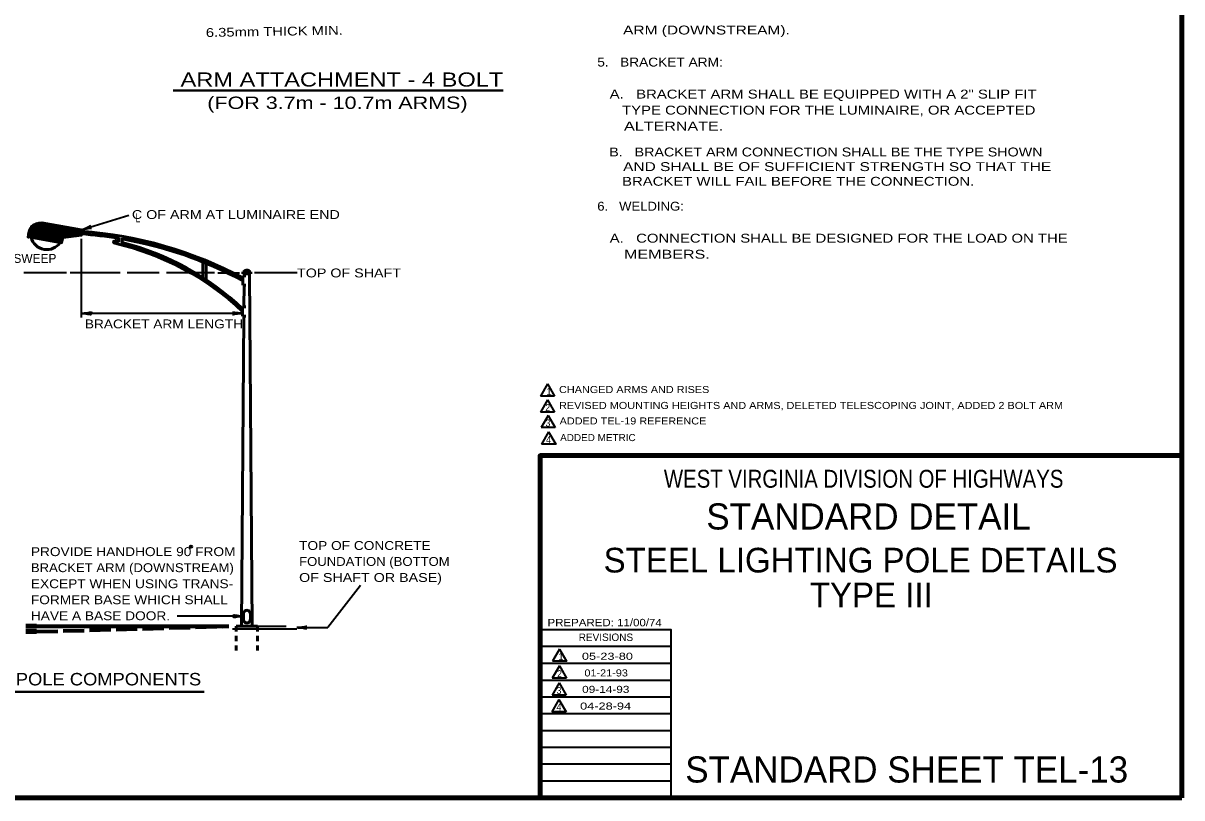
# Model space of a CAD drawing. Extents: x -23 to 690, y -228 to 443.
# Drawn here: x 356 to 684, y -0.6 to 218.8 of the extents above; entities that cross this region are included whole.
import ezdxf
from ezdxf.enums import TextEntityAlignment as Align

# ---------------------------------------------------------------- set-up
doc = ezdxf.new("R2010")
doc.units = 0
doc.header["$PDMODE"] = 32
doc.header["$PDSIZE"] = 0.5
doc.linetypes.add('LONG_DASHED', pattern=[7.5, 6, -1.5])
doc.linetypes.add('SHORT_DASHED', pattern=[2.7, 1.5, -1.2])
doc.layers.add('1', color=7, linetype='Continuous', lineweight=35)
doc.layers.add('61', color=7, linetype='Continuous', lineweight=35)

msp = doc.modelspace()

# ---------------------------------------------------------------- linework, layer by layer
at = {"layer": '1', "lineweight": 158}
for q in [(684.026, 437.805), (684.026, 96.305), (24.36, -0.611)]:
    msp.add_line((684.026, -0.611), q, dxfattribs=at)
at = {"layer": '1', "lineweight": 13}
msp.add_line((684.026, -0.611), (684.026, 437.805), dxfattribs=at)
at = {"layer": '1', "lineweight": 40}
for p, q in [((398.499, 199.759), (491.884, 199.759)), ((352.69, 29.414), (407.27, 29.414))]:
    msp.add_line(p, q, dxfattribs=at)
at = {"layer": '1'}
for p, q in [((372.45, 160.234), (385.87, 164.374)), ((372.45, 157.714), (372.45, 135.394)), ((368.291, 148.054), (356.21, 148.054)), ((383.411, 148.054), (369.31, 148.054)), ((394.51, 148.054), (385.43, 148.054)), ((410.13, 148.054), (396.53, 148.054)), ((411.13, 148.054), (417.19, 148.054)), ((433.57, 148.054), (421.47, 148.054)), ((418.13, 136.594), (372.45, 136.594)), ((504.445, 116.622), (502.445, 113.158)), ((504.445, 116.622), (506.445, 113.158)), ((506.445, 113.158), (502.445, 113.158)), ((504.445, 112.12), (502.445, 108.656)), ((504.445, 112.12), (506.445, 108.656)), ((506.445, 108.656), (502.445, 108.656)), ((504.612, 107.726), (502.612, 104.261)), ((504.612, 107.726), (506.612, 104.261)), ((506.612, 104.261), (502.612, 104.261)), ((504.76, 103.015), (502.76, 99.551)), ((451.49, 59.514), (442.231, 47.614)), ((418.39, 50.814), (399.55, 50.814)), ((415.291, 47.214), (433.43, 47.214)), ((422.351, 47.974), (430.411, 47.974)), ((433.43, 47.614), (442.231, 47.614)), ((539.443, 42.222), (502.36, 42.222)), ((507.823, 41.54), (505.823, 38.076)), ((539.443, 37.472), (502.36, 37.472)), ((507.788, 36.751), (505.788, 33.287)), ((507.788, 36.751), (509.788, 33.287)), ((509.788, 33.287), (505.788, 33.287)), ((539.443, 32.639), (502.36, 32.639)), ((507.746, 31.971), (505.746, 28.507)), ((507.746, 31.971), (509.746, 28.507)), ((539.443, 27.889), (502.36, 27.889)), ((507.692, 27.245), (505.692, 23.781)), ((509.746, 28.507), (505.746, 28.507)), ((507.692, 27.245), (509.692, 23.781)), ((539.443, 23.139), (502.36, 23.139)), ((509.692, 23.781), (505.692, 23.781)), ((539.443, 18.389), (502.36, 18.389)), ((539.443, 13.639), (502.36, 13.639)), ((539.443, 8.889), (502.36, 8.889)), ((539.443, 4.139), (502.36, 4.139))]:
    msp.add_line(p, q, dxfattribs=at)
at = {"layer": '1', "lineweight": 53}
for p, q in [((357.57, 159.554), (360.171, 162.134)), ((357.611, 159.674), (360.03, 162.094)), ((357.671, 159.834), (359.87, 162.054)), ((357.71, 159.994), (359.71, 161.994)), ((357.791, 160.194), (359.53, 161.914)), ((357.89, 160.394), (359.31, 161.814)), ((358.05, 160.654), (359.05, 161.654)), ((358.09, 159.954), (360.31, 162.154)), ((358.21, 159.954), (360.43, 162.194)), ((358.31, 159.954), (360.55, 162.194)), ((358.411, 159.954), (360.671, 162.214)), ((358.53, 159.954), (360.791, 162.214)), ((358.63, 159.954), (360.89, 162.214)), ((358.731, 159.954), (361.01, 162.214)), ((358.851, 159.954), (361.111, 162.214)), ((358.95, 159.954), (361.21, 162.214)), ((359.05, 159.954), (361.31, 162.214)), ((359.171, 159.954), (361.39, 162.194)), ((359.27, 159.954), (361.49, 162.174)), ((359.37, 159.954), (361.57, 162.154)), ((359.49, 159.954), (361.671, 162.134)), ((359.59, 159.954), (361.77, 162.134)), ((359.69, 159.954), (361.851, 162.114)), ((359.81, 159.954), (361.95, 162.094)), ((359.911, 159.954), (362.03, 162.074)), ((360.01, 159.954), (362.13, 162.054)), ((360.13, 159.954), (362.21, 162.054)), ((360.231, 159.954), (362.31, 162.034)), ((360.351, 159.954), (362.39, 162.014)), ((360.45, 159.954), (362.49, 161.994)), ((360.55, 159.954), (362.57, 161.974)), ((360.671, 159.954), (362.671, 161.974)), ((360.77, 159.954), (362.77, 161.954)), ((360.87, 159.954), (362.851, 161.934)), ((360.99, 159.954), (362.95, 161.914)), ((361.09, 159.954), (363.03, 161.894)), ((361.19, 159.954), (363.13, 161.894)), ((361.31, 159.954), (363.21, 161.874)), ((361.411, 159.954), (363.31, 161.854)), ((361.51, 159.954), (363.39, 161.834)), ((361.63, 159.954), (363.49, 161.814)), ((361.731, 159.954), (363.57, 161.794)), ((361.83, 159.954), (363.671, 161.794)), ((361.95, 159.954), (363.77, 161.774)), ((362.05, 159.954), (363.851, 161.754)), ((362.15, 159.954), (363.95, 161.734)), ((362.27, 159.954), (364.03, 161.714)), ((362.37, 159.954), (364.13, 161.714)), ((362.471, 159.954), (364.21, 161.694)), ((362.59, 159.954), (364.31, 161.674)), ((362.69, 159.954), (364.39, 161.654)), ((362.791, 159.954), (364.49, 161.634)), ((362.911, 159.954), (364.57, 161.634)), ((363.01, 159.954), (364.671, 161.614)), ((363.13, 159.954), (364.77, 161.594)), ((363.231, 159.954), (364.851, 161.574)), ((363.33, 159.954), (364.95, 161.554)), ((363.45, 159.954), (365.03, 161.554)), ((363.55, 159.954), (365.13, 161.534)), ((363.65, 159.954), (365.21, 161.514)), ((363.77, 159.954), (365.31, 161.494)), ((363.87, 159.954), (365.39, 161.474)), ((363.971, 159.954), (365.49, 161.474)), ((364.09, 159.954), (365.57, 161.454)), ((364.19, 159.954), (365.671, 161.434)), ((364.291, 159.954), (365.77, 161.414)), ((364.411, 159.954), (365.851, 161.394)), ((364.51, 159.954), (365.95, 161.394)), ((364.611, 159.954), (366.03, 161.374)), ((364.731, 159.954), (366.13, 161.354)), ((364.83, 159.954), (366.21, 161.334)), ((364.93, 159.954), (366.31, 161.314)), ((365.05, 159.954), (366.39, 161.314)), ((365.15, 159.954), (366.49, 161.294)), ((365.25, 159.954), (366.57, 161.274)), ((365.37, 159.954), (366.671, 161.254)), ((365.471, 159.954), (366.77, 161.234)), ((365.57, 159.954), (366.851, 161.234)), ((365.69, 159.954), (366.95, 161.214)), ((365.791, 159.954), (367.03, 161.194)), ((365.89, 159.954), (367.13, 161.174)), ((366.01, 159.954), (367.21, 161.154)), ((366.111, 159.954), (367.31, 161.154)), ((366.231, 159.954), (367.39, 161.134)), ((366.33, 159.954), (367.49, 161.114)), ((366.43, 159.954), (367.57, 161.094)), ((366.55, 159.954), (367.671, 161.074)), ((366.65, 159.954), (367.75, 161.074)), ((366.75, 159.954), (367.851, 161.054)), ((366.87, 159.954), (367.95, 161.034)), ((366.971, 159.954), (368.03, 161.014)), ((367.07, 159.954), (368.13, 160.994)), ((367.19, 159.954), (368.21, 160.994)), ((367.291, 159.954), (368.31, 160.974)), ((367.39, 159.954), (368.39, 160.954)), ((367.51, 159.954), (368.49, 160.934)), ((367.611, 159.954), (368.57, 160.914)), ((367.71, 159.954), (368.671, 160.914)), ((367.83, 159.954), (368.75, 160.894)), ((367.93, 159.954), (368.851, 160.874)), ((368.03, 159.954), (368.95, 160.854)), ((368.15, 159.954), (369.03, 160.834)), ((368.25, 159.954), (369.13, 160.834)), ((368.351, 159.954), (369.21, 160.814)), ((368.471, 159.954), (369.31, 160.794)), ((368.57, 159.954), (369.39, 160.774)), ((368.671, 159.954), (369.49, 160.754)), ((368.791, 159.954), (369.57, 160.754)), ((357.49, 159.034), (358.231, 159.774)), ((357.49, 158.914), (358.33, 159.774)), ((357.49, 158.814), (358.45, 159.774)), ((357.49, 158.714), (358.55, 159.774)), ((357.49, 158.594), (358.65, 159.774)), ((357.49, 158.514), (358.77, 159.774)), ((357.51, 159.154), (358.111, 159.774)), ((357.51, 158.414), (358.87, 159.774)), ((357.51, 158.314), (358.971, 159.774)), ((357.53, 159.274), (358.07, 159.834)), ((357.55, 159.414), (358.07, 159.934)), ((357.57, 158.254), (359.09, 159.774)), ((357.671, 158.234), (359.19, 159.774)), ((357.75, 158.234), (359.291, 159.774)), ((357.851, 158.214), (359.411, 159.774)), ((357.93, 158.194), (359.51, 159.774)), ((358.03, 158.174), (359.611, 159.774)), ((358.111, 158.154), (359.731, 159.774)), ((358.21, 158.154), (359.83, 159.774)), ((358.31, 158.134), (359.93, 159.774)), ((358.39, 158.114), (360.05, 159.774)), ((358.49, 158.094), (360.15, 159.774)), ((358.57, 158.074), (360.25, 159.774)), ((358.671, 158.074), (360.37, 159.774)), ((358.75, 158.054), (360.471, 159.774)), ((358.851, 158.034), (360.57, 159.774)), ((358.93, 158.014), (360.69, 159.774)), ((359.03, 157.994), (360.791, 159.774)), ((359.111, 157.994), (360.89, 159.774)), ((359.21, 157.974), (361.01, 159.774)), ((359.291, 157.954), (361.111, 159.774)), ((359.39, 157.934), (361.231, 159.774)), ((359.49, 157.914), (361.33, 159.774)), ((359.57, 157.914), (361.43, 159.774)), ((359.671, 157.894), (361.55, 159.774)), ((359.75, 157.874), (361.65, 159.774)), ((359.851, 157.854), (361.75, 159.774)), ((359.93, 157.834), (361.87, 159.774)), ((360.03, 157.834), (361.971, 159.774)), ((360.111, 157.814), (362.07, 159.774)), ((360.21, 157.794), (362.19, 159.774)), ((360.291, 157.774), (362.291, 159.774)), ((360.39, 157.754), (362.39, 159.774)), ((360.49, 157.754), (362.51, 159.774)), ((360.57, 157.734), (362.611, 159.774)), ((360.671, 157.714), (362.71, 159.774)), ((360.75, 157.694), (362.83, 159.774)), ((360.851, 157.674), (362.93, 159.774)), ((360.93, 157.674), (363.03, 159.774)), ((361.03, 157.654), (363.15, 159.774)), ((361.111, 157.634), (363.25, 159.774)), ((361.21, 157.614), (363.351, 159.774)), ((361.291, 157.594), (363.471, 159.774)), ((361.39, 157.574), (363.57, 159.774)), ((361.49, 157.574), (363.671, 159.774)), ((361.57, 157.554), (363.791, 159.774)), ((361.671, 157.534), (363.89, 159.774)), ((361.75, 157.514), (364.01, 159.774)), ((361.851, 157.494), (364.111, 159.774)), ((361.93, 157.494), (364.21, 159.774)), ((362.03, 157.474), (364.33, 159.774)), ((362.111, 157.454), (364.43, 159.774)), ((362.21, 157.434), (364.53, 159.774)), ((362.291, 157.414), (364.65, 159.774)), ((362.39, 157.414), (364.75, 159.774)), ((362.49, 157.394), (364.851, 159.774)), ((362.57, 157.374), (364.971, 159.774)), ((362.671, 157.354), (365.07, 159.774)), ((362.75, 157.334), (365.171, 159.774)), ((362.851, 157.334), (365.291, 159.774)), ((362.93, 157.314), (365.39, 159.774)), ((363.03, 157.294), (365.49, 159.774)), ((363.111, 157.274), (365.611, 159.774)), ((363.21, 157.254), (365.71, 159.774)), ((363.291, 157.254), (365.81, 159.774)), ((363.39, 157.234), (365.93, 159.774)), ((363.49, 157.214), (366.03, 159.774)), ((363.57, 157.194), (366.13, 159.774)), ((363.671, 157.174), (366.25, 159.774)), ((363.75, 157.174), (366.351, 159.774)), ((363.851, 157.154), (366.45, 159.774)), ((363.93, 157.134), (366.57, 159.774)), ((364.03, 157.114), (366.671, 159.774)), ((364.111, 157.094), (366.791, 159.774)), ((364.21, 157.094), (366.89, 159.774)), ((364.291, 157.074), (366.99, 159.774)), ((364.39, 157.054), (367.111, 159.774)), ((364.49, 157.034), (367.21, 159.774)), ((364.57, 157.014), (367.31, 159.774)), ((364.671, 157.014), (367.43, 159.774)), ((364.75, 156.994), (367.53, 159.774)), ((364.851, 156.974), (367.63, 159.774)), ((364.93, 156.954), (367.75, 159.774)), ((365.03, 156.934), (367.851, 159.774)), ((365.111, 156.934), (367.95, 159.774)), ((365.21, 156.914), (368.07, 159.774)), ((365.291, 156.894), (368.171, 159.774)), ((365.39, 156.874), (368.27, 159.774)), ((365.49, 156.854), (368.39, 159.774)), ((365.57, 156.854), (368.49, 159.774)), ((365.671, 156.834), (368.59, 159.774)), ((365.75, 156.814), (368.71, 159.774)), ((365.851, 156.794), (368.81, 159.774)), ((365.93, 156.774), (367.19, 158.034)), ((366.03, 156.774), (367.171, 157.894)), ((366.111, 156.754), (367.13, 157.754)), ((366.21, 156.734), (367.09, 157.634)), ((366.291, 156.714), (367.07, 157.494)), ((367.231, 158.094), (368.911, 159.774)), ((367.37, 158.094), (369.03, 159.774)), ((367.49, 158.114), (369.13, 159.774)), ((367.611, 158.134), (369.231, 159.774)), ((367.731, 158.154), (369.351, 159.774)), ((367.851, 158.154), (369.45, 159.774)), ((367.971, 158.174), (369.55, 159.774)), ((368.09, 158.194), (369.671, 159.774)), ((368.21, 158.214), (369.77, 159.774)), ((368.33, 158.214), (369.89, 159.774)), ((368.45, 158.234), (369.99, 159.774)), ((368.57, 158.254), (370.09, 159.774)), ((368.71, 158.274), (370.21, 159.774)), ((368.83, 158.274), (370.31, 159.774)), ((368.89, 159.954), (369.671, 160.734)), ((368.95, 158.294), (370.411, 159.774)), ((369.01, 159.954), (369.75, 160.714)), ((369.07, 158.314), (370.53, 159.774)), ((369.111, 159.954), (369.851, 160.694)), ((369.19, 158.334), (370.63, 159.774)), ((369.21, 159.954), (369.95, 160.674)), ((369.31, 158.334), (370.731, 159.774)), ((369.33, 159.954), (370.03, 160.674)), ((369.43, 159.954), (370.13, 160.654)), ((369.43, 158.354), (370.851, 159.774)), ((369.53, 159.954), (370.21, 160.634)), ((369.55, 158.374), (370.95, 159.774)), ((369.65, 159.954), (370.31, 160.614)), ((369.671, 158.394), (371.05, 159.774)), ((369.75, 159.954), (370.39, 160.594)), ((369.791, 158.394), (371.171, 159.774)), ((369.851, 159.954), (370.49, 160.594)), ((369.911, 158.414), (371.27, 159.774)), ((369.971, 159.954), (370.57, 160.574)), ((370.05, 158.434), (371.37, 159.774)), ((370.07, 159.954), (370.671, 160.554)), ((370.171, 159.954), (370.75, 160.534)), ((370.171, 158.454), (371.49, 159.774)), ((370.291, 159.954), (370.851, 160.514)), ((370.291, 158.454), (371.59, 159.774)), ((370.39, 159.954), (370.95, 160.514)), ((370.411, 158.474), (371.69, 159.774)), ((370.49, 159.954), (371.03, 160.494)), ((370.53, 158.494), (371.81, 159.774)), ((370.611, 159.954), (371.13, 160.474)), ((370.65, 158.514), (371.911, 159.774)), ((370.71, 159.954), (371.21, 160.454)), ((370.77, 158.514), (372.01, 159.774)), ((370.81, 159.954), (371.31, 160.434)), ((370.89, 158.534), (372.45, 160.094)), ((370.93, 159.954), (371.39, 160.434)), ((371.01, 158.554), (372.45, 159.994)), ((371.03, 159.954), (371.49, 160.414)), ((371.13, 159.954), (371.57, 160.394)), ((371.13, 158.574), (372.45, 159.874)), ((371.25, 159.954), (371.671, 160.374)), ((371.27, 158.574), (372.45, 159.774)), ((371.351, 159.954), (371.75, 160.354)), ((371.39, 158.594), (372.45, 159.674)), ((371.45, 159.954), (371.851, 160.354)), ((371.51, 158.614), (372.45, 159.554)), ((371.57, 159.954), (371.95, 160.334)), ((371.63, 158.634), (372.45, 159.454)), ((371.671, 159.954), (372.03, 160.314)), ((371.75, 158.634), (372.45, 159.354)), ((371.791, 159.954), (372.13, 160.294)), ((371.87, 158.654), (372.45, 159.234)), ((371.89, 159.954), (372.21, 160.274)), ((371.99, 159.954), (372.31, 160.274)), ((371.99, 158.674), (372.45, 159.134)), ((372.07, 159.934), (372.39, 160.254)), ((372.07, 159.834), (372.45, 160.194)), ((372.111, 158.694), (372.45, 159.034)), ((372.231, 158.694), (372.45, 158.914)), ((372.351, 158.714), (372.45, 158.814)), ((383.03, 156.754), (383.03, 158.034)), ((383.99, 156.514), (383.99, 157.874)), ((366.39, 156.694), (367.03, 157.354)), ((366.471, 156.694), (367.01, 157.214)), ((366.57, 156.674), (366.971, 157.074)), ((366.671, 156.654), (366.93, 156.934)), ((366.75, 156.634), (366.911, 156.794)), ((366.851, 156.614), (366.87, 156.654)), ((406.851, 146.714), (406.851, 151.174)), ((407.791, 146.114), (407.791, 150.774)), ((418.19, 148.334), (420.47, 148.334)), ((418.19, 148.334), (418.19, 147.774)), ((418.19, 147.774), (420.47, 147.774)), ((418.57, 147.774), (418.57, 147.194)), ((420.83, 47.974), (420.09, 147.774)), ((420.47, 148.334), (420.47, 147.774)), ((419.07, 147.194), (418.19, 147.194)), ((418.19, 147.194), (418.19, 144.554)), ((419.07, 144.554), (418.19, 144.554)), ((418.55, 144.554), (418.51, 138.494)), ((419.01, 138.494), (418.13, 138.494)), ((418.13, 138.494), (418.13, 135.854)), ((418.49, 135.854), (417.81, 47.974)), ((419.01, 135.854), (418.13, 135.854)), ((418.33, 49.994), (418.33, 51.494)), ((420.33, 49.994), (420.33, 51.494)), ((416.31, 47.974), (422.351, 47.974))]:
    msp.add_line(p, q, dxfattribs=at)
at = {"layer": '1', "lineweight": 106}
for p, q in [((356.77, 47.974), (359.81, 47.974)), ((356.77, 46.454), (359.81, 46.454))]:
    msp.add_line(p, q, dxfattribs=at)
at = {"layer": '1', "lineweight": 70}
msp.add_line((359.81, 47.974), (414.231, 47.974), dxfattribs=at)
at = {"layer": '1', "linetype": 'LONG_DASHED', "lineweight": 70}
msp.add_line((359.81, 46.454), (414.231, 47.974), dxfattribs=at)
at = {"layer": '1', "linetype": 'SHORT_DASHED', "lineweight": 53}
for p, q in [((416.31, 47.974), (416.31, 39.914)), ((422.351, 47.974), (422.351, 39.914))]:
    msp.add_line(p, q, dxfattribs=at)
at = {"layer": '1', "lineweight": 53}
msp.add_lwpolyline([(361.291, 162.214), (372.45, 160.234), (372.45, 158.734), (367.21, 158.074), (366.87, 156.614), (357.53, 158.274)], dxfattribs=at)
msp.add_lwpolyline([(358.07, 159.954), (372.07, 159.954), (372.07, 159.774), (358.07, 159.774)], close=True, dxfattribs=at)
at = {"layer": '1'}
for points in [[(504.76, 103.015), (506.76, 99.551), (502.76, 99.551)], [(539.443, -0.611), (539.443, 46.972), (502.36, 46.972)], [(507.823, 41.54), (509.823, 38.076), (505.823, 38.076)]]:
    msp.add_lwpolyline(points, dxfattribs=at)
at = {"layer": '1', "lineweight": 158}
msp.add_lwpolyline([(502.36, -0.611), (502.36, 96.305), (684.026, 96.305)], dxfattribs=at)
at = {"layer": '1'}
msp.add_circle((403.483, 70.491), 0.325, dxfattribs=at)
at = {"layer": '1', "lineweight": 53}
for centre, radius, start, end in [((360.941, 158.77), 3.456, 84.23953, 188.38162), ((362.702, 159.236), 4.57, 193.94762, 326.05059), ((364.26, 45.866), 114.289, 61.84402, 85.88743), ((364.26, 45.11), 114.289, 80.54208, 85.88743), ((364.26, 45.11), 114.289, 61.84402, 80.06146), ((381.968, 156.837), 0.383, 99.37484, 260.62516), ((382.081, 157.086), 0.651, 235.53017, 254.38288), ((364.379, 80.626), 78.568, 76.2603, 77.11012), ((364.379, 79.87), 78.568, 46.83897, 77.11012), ((364.379, 80.626), 78.568, 46.83897, 75.54976), ((419.328, 148.052), 0.802, 20.3922, 159.6078), ((419.328, 51.521), 0.993, 358.58875, 181.41125), ((419.328, 49.949), 0.993, 178.58875, 1.41125)]:
    msp.add_arc(centre, radius, start, end, dxfattribs=at)
at = {"layer": '1', "lineweight": 40}
for centre, major_axis, ratio, start_param, end_param in [((373.425, 160.829), (-1.674, -0.68), 0.122415, 0.8963533, 3.1415927), ((373.598, 160.367), (1.744, 0.352), 0.07063, 6.2823074, 8.5597026), ((373.585, 136.385), (-1.77, 0.177), 0.07063, 3.1407148, 5.41811), ((373.585, 136.385), (-1.77, 0.177), 0.07063, 3.1407148, 5.41811), ((373.556, 136.876), (-1.8, -0.157), 0.122415, 0.8963533, 3.1415927), ((373.556, 136.876), (-1.8, -0.157), 0.122415, 0.8963533, 3.1415927), ((417.024, 136.319), (1.8, 0.157), 0.122415, 0.8963533, 3.1415927), ((417.024, 136.319), (1.8, 0.157), 0.122415, 0.8963533, 3.1415927), ((416.994, 136.811), (1.77, -0.177), 0.07063, 3.1407148, 5.41811), ((416.994, 136.811), (1.77, -0.177), 0.07063, 3.1407148, 5.41811), ((417.298, 50.538), (1.8, 0.157), 0.122415, 0.8963533, 3.1415927), ((417.268, 51.03), (1.77, -0.177), 0.07063, 3.1407148, 5.41811), ((434.565, 47.396), (-1.77, 0.177), 0.07063, 3.1407148, 5.41811), ((434.536, 47.888), (-1.8, -0.157), 0.122415, 0.8963533, 3.1415927)]:
    msp.add_ellipse(centre, major_axis=major_axis, ratio=ratio, start_param=start_param, end_param=end_param, dxfattribs=at)
at = {"layer": '1'}
for p in [(358.53, 161.234), (357.53, 158.274)]:
    msp.add_point(p, dxfattribs=at)
at = {"layer": '61', "lineweight": 53}
for q in [(556.776, -0.611), (556.776, -0.611), (556.776, -0.611), (557.026, -0.611), (557.026, -0.611)]:
    msp.add_line((684.026, -0.611), q, dxfattribs=at)

# ---------------------------------------------------------------- texts
at = {"layer": '1', "width": 1.25}
msp.add_text('6.35mm THICK MIN.', height=2.5, rotation=1, dxfattribs=at).set_placement((407.73, 214.882))
at = {"layer": '1'}
for s, height, width, p in [('      ARM (DOWNSTREAM).', 2.52, 1.3, (518.531, 215.597)), ('5.   BRACKET ARM:', 2.52, 1.15, (518.531, 206.517)), ('ARM ATTACHMENT - 4 BOLT', 4, 1.25, (400.54, 200.841)), ('(FOR 3.7m - 10.7m ARMS)', 3.5, 1.3, (408.115, 194.502)), ('   A.   BRACKET ARM SHALL BE EQUIPPED WITH A 2" SLIP FIT', 2.52, 1.25, (518.531, 197.457)), ('      TYPE CONNECTION FOR THE LUMINAIRE, OR ACCEPTED', 2.52, 1.25, (518.531, 192.917)), ('      ALTERNATE.', 2.52, 1.35, (518.531, 188.397)), ('   B.   BRACKET ARM CONNECTION SHALL BE THE TYPE SHOWN', 2.52, 1.2, (518.531, 181.05)), ('      AND SHALL BE OF SUFFICIENT STRENGTH SO THAT THE', 2.52, 1.3, (518.531, 176.91)), ('      BRACKET WILL FAIL BEFORE THE CONNECTION.', 2.52, 1.25, (518.531, 172.75)), ('6.   WELDING:', 2.52, 1.1, (518.531, 165.697)), ('C OF ARM AT LUMINAIRE END', 2.52, 1.2, (386.77, 163.334)), ('L', 2.52, 0.75, (387.791, 162.414)), ('   A.   CONNECTION SHALL BE DESIGNED FOR THE LOAD ON THE', 2.52, 1.25, (518.531, 156.637)), ('      MEMBERS. ', 2.52, 1.35, (518.531, 152.097)), ('TOP OF SHAFT', 2.52, 1.2, (433.53, 146.794)), ('BRACKET ARM LENGTH', 2.52, 1.15, (373.45, 132.354)), ('CHANGED ARMS AND RISES', 2, 1.15, (507.701, 114.032)), ('REVISED MOUNTING HEIGHTS AND ARMS, DELETED TELESCOPING JOINT, ADDED 2 BOLT ARM', 2, 1.15, (507.701, 109.53)), ('2', 2, 0.9, (503.822, 108.908)), ('3', 2, 0.9, (503.887, 104.545)), ('ADDED TEL-19 REFERENCE', 2, 1.15, (507.869, 105.135)), ('4', 2, 0.95, (504.034, 99.834)), ('ADDED METRIC', 2, 1.05, (508.016, 100.424)), ('PROVIDE HANDHOLE 90 FROM', 2.52, 1.15, (358.171, 67.854)), ('TOP OF CONCRETE', 2.52, 1.15, (434.111, 69.594)), ('BRACKET ARM (DOWNSTREAM)', 2.52, 1.1, (358.171, 63.314)), ('FOUNDATION (BOTTOM', 2.52, 1.1, (434.111, 65.074)), ('OF SHAFT OR BASE)', 2.52, 1.2, (434.111, 60.534)), ('EXCEPT WHEN USING TRANS-', 2.52, 1.15, (358.171, 58.774)), ('FORMER BASE WHICH SHALL', 2.52, 1.15, (358.171, 54.234)), ('HAVE A BASE DOOR.', 2.52, 1.15, (358.171, 49.694)), ('PREPARED: 11/00/74', 2.114, 1.15, (504.443, 47.972)), ('POLE COMPONENTS', 3.528, 1.1, (353.911, 31.234)), ('2', 2, 0.9, (507.161, 33.547)), ('3', 2, 0.9, (507.02, 28.791)), ('4', 2, 0.95, (506.966, 24.064))]:
    msp.add_text(s, height=height, dxfattribs=dict(at, width=width)).set_placement(p)
for s, height, p in [('UPSWEEP', 2.52, (348.55, 150.914)), ('1', 2, (504.132, 113.487)), ('REVISIONS', 2.114, (513.276, 43.805)), ('1', 2, (507.511, 38.405)), ('STANDARD SHEET TEL-13', 7.401, (543.443, 3.722))]:
    msp.add_text(s, height=height, dxfattribs=at).set_placement(p)
for s, height, width, p in [('WEST VIRGINIA DIVISION OF HIGHWAYS', 5.074, 0.85, (593.943, 87.222)), ('05-23-80', 2, 1.35, (521.395, 38.486)), ('01-21-93', 2, 1.15, (521.044, 33.766)), ('09-14-93', 2, 1.25, (520.936, 29.11)), ('04-28-94', 2, 1.35, (520.89, 24.383))]:
    msp.add_text(s, height=height, dxfattribs=dict(at, width=width)).set_placement(p, align=Align.CENTER)
for s, height, p in [('STANDARD DETAIL', 7.401, (595.318, 75.389)), ('STEEL LIGHTING POLE DETAILS', 6.993, (593.075, 63.212)), ('TYPE III', 6.993, (596.105, 53.362))]:
    msp.add_text(s, height=height, dxfattribs=at).set_placement(p, align=Align.CENTER)

doc.saveas('drawing.dxf')
